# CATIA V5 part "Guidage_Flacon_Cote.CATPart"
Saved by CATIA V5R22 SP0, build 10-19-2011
Part number: Guidage_flacon_cote1
Bounding box of the stored display mesh (mm): x -5 to 5, y -49.5 to 49.5, z 0 to 15
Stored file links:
  C:\Users\La forge\Desktop\CAO_PER_pick&place_2023A\Sous_Ensemble_Flacon\Guidage_Flacon_Cote.CATPart
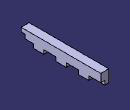
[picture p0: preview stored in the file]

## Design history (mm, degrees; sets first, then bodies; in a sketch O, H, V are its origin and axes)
Body1 (main body)
  Sketch1 on yz-plane, origin (0, 0, 0), H (0, 1, 0), V (0, 0, 1)
    point P1 (49.5, 0)
    line L1 (49.5, 0) -> (-49.5, 0)
    line L2 (-49.5, 0) -> (-49.5, 15)
    line L3 (-49.5, 15) -> (49.5, 15)
    line L4 (49.5, 15) -> (49.5, 0)
    length L3 = 99
    length L4 = 15
    coincidence: P1 H
    horizontal: L1 H, L3 H
    vertical: L2 V, L4 V
    equidistance: L4 L2 O
  Pad1: profile Sketch1, direction (1, 0, 0), length 5
  Sketch2 on end face of Pad1, origin (5, 0, 0), H (0, 1, 0), V (0, 0, 1)
    point P1 (-49.5, 0)
    line L1 (-49.5, 0) -> (-34.5, 0)
    line L2 (-34.5, 0) -> (-34.5, 5)
    line L3 (-34.5, 5) -> (-49.5, 5)
    line L4 (-49.5, 5) -> (-49.5, 0)
    reference projected point E1 (-49.5, 0) from vertex [face of Pad1 from Sketch1.L1 | end face of Pad1 | face of Pad1 from Sketch1.L2]
    length L2 = 5
    length L3 = 15
    coincidence: P1 H, P1 E1
    horizontal: L1 H, L3 H
    vertical: L2 V, L4 V
  Pocket1: profile Sketch2, direction (-1, 0, 0), through (limit type 3)
  RectPattern1: of Pocket1, direction 1 instances 4, spacing 28, along end face of Pad1
  Sketch3 on end face of Pad1, origin (5, 0, 0), H (0, 1, 0), V (0, 0, 1)
    line L1 (-44.5, 5) -> (-49.5, 5)
    line L2 (-49.5, 5) -> (-49.5, 10)
    line L3 (-49.5, 10) -> (-44.5, 10)
    line L4 (-44.5, 10) -> (-44.5, 5)
    reference projected line E1 (-34.5, 5) -> (-49.5, 5) from edge [end face of Pad1 | face of Pocket1 from Sketch2.L3]
    reference projected line E2 (-49.5, 15) -> (-49.5, 0) from edge [face of Pad1 from Sketch1.L2 | end face of Pad1]
    length L2 = 5
    length L3 = 5
    horizontal: L1 H, L3 H
    vertical: L2 V, L4 V
    coincidence: L1 E1, L2 E2
  Pocket2: profile Sketch3, direction (-1, 0, 0), through (limit type 3)
  Sketch4 on yz-plane, origin (0, 0, 0), H (0, 1, 0), V (0, 0, 1)
    point P1 (49.5, 0)
    line L1 (49.5, 0) -> (-49.5, 0)
    line L2 (-49.5, 0) -> (-49.5, 15)
    line L3 (-49.5, 15) -> (49.5, 15)
    line L4 (49.5, 15) -> (49.5, 0)
    length L3 = 99
    length L4 = 15
    coincidence: P1 H
    horizontal: L1 H, L3 H
    vertical: L2 V, L4 V
    equidistance: L4 L2 O
  Pad2: profile Sketch4, direction (-1, 0, 0), length 5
